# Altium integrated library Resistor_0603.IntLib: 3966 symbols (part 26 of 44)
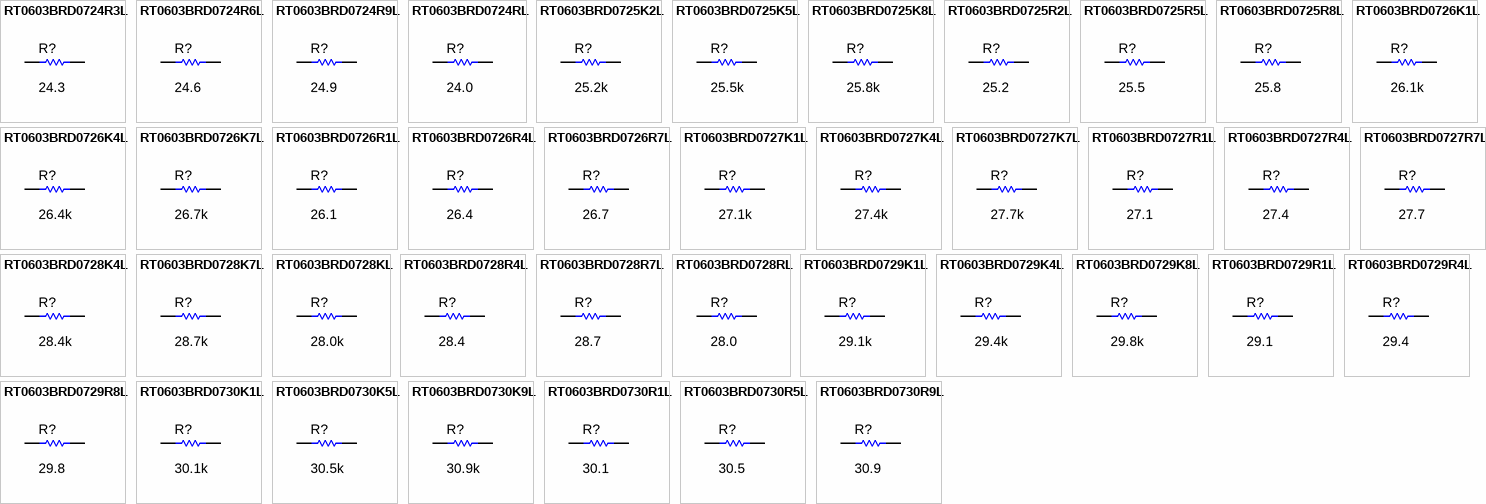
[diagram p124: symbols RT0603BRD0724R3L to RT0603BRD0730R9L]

## RT0603BRD0728R7L
designator R?  ValueDisplayed: 28.7  (hidden comment: RT0603BRD0728R7L)
RES, 28.7, 0.1%, 0.1 W, 0603; Manufacturer: Yageo America; CompType: Resistor; Value: 28.7; Value_Code: 28R7; Tolerance_%: 0.1; Value2: 0.1W; VDC_V: 75; TempCo: 25 ppm/C; SizeArea_mm2: 1.28; SizeX_mm: 1.6; SizeY_mm: 0.8; SizeZ_mm: 1; EIA_Code: E192; U/M: EA; AEC Category: Q200
signal-integrity model Resistor
simulation model Resistor
footprint 0603
footprint 0603M
footprint 0603L
footprint 0603_HV
footprint 0603S
pins: 1, 2

## RT0603BRD0728RL
designator R?  ValueDisplayed: 28.0  (hidden comment: RT0603BRD0728RL)
RES, 28.0, 0.1%, 0.1 W, 0603; Manufacturer: Yageo America; CompType: Resistor; Value: 28.0; Res_ohm: 28; Value_Code: 28R0; Tolerance_%: 0.1; Value2: 0.1W; VDC_V: 75; TempCo: 25 ppm/C; SizeArea_mm2: 1.28; SizeX_mm: 1.6; SizeY_mm: 0.8; SizeZ_mm: 1; EIA_Code: E192; U/M: EA; AEC Category: Q200
signal-integrity model Resistor
simulation model Resistor
footprint 0603
footprint 0603M
footprint 0603L
footprint 0603_HV
footprint 0603S
pins: 1, 2

## RT0603BRD0729K1L
designator R?  ValueDisplayed: 29.1k  (hidden comment: RT0603BRD0729K1L)
RES, 29.1 k, 0.1%, 0.1 W, 0603; Manufacturer: Yageo America; CompType: Resistor; Value: 29.1k; Res_ohm: 29100; Value_Code: 29k1; Tolerance_%: 0.1; Value2: 0.1W; VDC_V: 75; TempCo: 25 ppm/C; SizeArea_mm2: 1.28; SizeX_mm: 1.6; SizeY_mm: 0.8; SizeZ_mm: 1; EIA_Code: E192; U/M: EA; AEC Category: Q200
signal-integrity model Resistor
simulation model Resistor
footprint 0603
footprint 0603M
footprint 0603L
footprint 0603_HV
footprint 0603S
pins: 1, 2

## RT0603BRD0729K4L
designator R?  ValueDisplayed: 29.4k  (hidden comment: RT0603BRD0729K4L)
RES, 29.4 k, 0.1%, 0.1 W, 0603; Manufacturer: Yageo America; CompType: Resistor; Value: 29.4k; Res_ohm: 29400; Value_Code: 29k4; Tolerance_%: 0.1; Value2: 0.1W; VDC_V: 75; TempCo: 25 ppm/C; SizeArea_mm2: 1.28; SizeX_mm: 1.6; SizeY_mm: 0.8; SizeZ_mm: 1; EIA_Code: E192; U/M: EA; AEC Category: Q200
signal-integrity model Resistor
simulation model Resistor
footprint 0603
footprint 0603M
footprint 0603L
footprint 0603_HV
footprint 0603S
pins: 1, 2

## RT0603BRD0729K8L
designator R?  ValueDisplayed: 29.8k  (hidden comment: RT0603BRD0729K8L)
RES, 29.8 k, 0.1%, 0.1 W, 0603; Manufacturer: Yageo America; CompType: Resistor; Value: 29.8k; Res_ohm: 29800; Value_Code: 29k8; Tolerance_%: 0.1; Value2: 0.1W; VDC_V: 75; TempCo: 25 ppm/C; SizeArea_mm2: 1.28; SizeX_mm: 1.6; SizeY_mm: 0.8; SizeZ_mm: 1; EIA_Code: E192; U/M: EA; AEC Category: Q200
signal-integrity model Resistor
simulation model Resistor
footprint 0603
footprint 0603M
footprint 0603L
footprint 0603_HV
footprint 0603S
pins: 1, 2

## RT0603BRD0729R1L
designator R?  ValueDisplayed: 29.1  (hidden comment: RT0603BRD0729R1L)
RES, 29.1, 0.1%, 0.1 W, 0603; Manufacturer: Yageo America; CompType: Resistor; Value: 29.1; Value_Code: 29R1; Tolerance_%: 0.1; Value2: 0.1W; VDC_V: 75; TempCo: 25 ppm/C; SizeArea_mm2: 1.28; SizeX_mm: 1.6; SizeY_mm: 0.8; SizeZ_mm: 1; EIA_Code: E192; U/M: EA; AEC Category: Q200
signal-integrity model Resistor
simulation model Resistor
footprint 0603
footprint 0603M
footprint 0603L
footprint 0603_HV
footprint 0603S
pins: 1, 2

## RT0603BRD0729R4L
designator R?  ValueDisplayed: 29.4  (hidden comment: RT0603BRD0729R4L)
RES, 29.4, 0.1%, 0.1 W, 0603; Manufacturer: Yageo America; CompType: Resistor; Value: 29.4; Value_Code: 29R4; Tolerance_%: 0.1; Value2: 0.1W; VDC_V: 75; TempCo: 25 ppm/C; SizeArea_mm2: 1.28; SizeX_mm: 1.6; SizeY_mm: 0.8; SizeZ_mm: 1; EIA_Code: E192; U/M: EA; AEC Category: Q200
signal-integrity model Resistor
simulation model Resistor
footprint 0603
footprint 0603M
footprint 0603L
footprint 0603_HV
footprint 0603S
pins: 1, 2

## RT0603BRD0729R8L
designator R?  ValueDisplayed: 29.8  (hidden comment: RT0603BRD0729R8L)
RES, 29.8, 0.1%, 0.1 W, 0603; Manufacturer: Yageo America; CompType: Resistor; Value: 29.8; Value_Code: 29R8; Tolerance_%: 0.1; Value2: 0.1W; VDC_V: 75; TempCo: 25 ppm/C; SizeArea_mm2: 1.28; SizeX_mm: 1.6; SizeY_mm: 0.8; SizeZ_mm: 1; EIA_Code: E192; U/M: EA; AEC Category: Q200
signal-integrity model Resistor
simulation model Resistor
footprint 0603
footprint 0603M
footprint 0603L
footprint 0603_HV
footprint 0603S
pins: 1, 2

## RT0603BRD0730K1L
designator R?  ValueDisplayed: 30.1k  (hidden comment: RT0603BRD0730K1L)
RES, 30.1 k, 0.1%, 0.1 W, 0603; Manufacturer: Yageo America; CompType: Resistor; Value: 30.1k; Res_ohm: 30100; Value_Code: 30k1; Tolerance_%: 0.1; Value2: 0.1W; VDC_V: 75; TempCo: 25 ppm/C; SizeArea_mm2: 1.28; SizeX_mm: 1.6; SizeY_mm: 0.8; SizeZ_mm: 1; EIA_Code: E192; U/M: EA; AEC Category: Q200
signal-integrity model Resistor
simulation model Resistor
footprint 0603
footprint 0603M
footprint 0603L
footprint 0603_HV
footprint 0603S
pins: 1, 2

## RT0603BRD0730K5L
designator R?  ValueDisplayed: 30.5k  (hidden comment: RT0603BRD0730K5L)
RES, 30.5 k, 0.1%, 0.1 W, 0603; Manufacturer: Yageo America; CompType: Resistor; Value: 30.5k; Res_ohm: 30500; Value_Code: 30k5; Tolerance_%: 0.1; Value2: 0.1W; VDC_V: 75; TempCo: 25 ppm/C; SizeArea_mm2: 1.28; SizeX_mm: 1.6; SizeY_mm: 0.8; SizeZ_mm: 1; EIA_Code: E192; U/M: EA; AEC Category: Q200
signal-integrity model Resistor
simulation model Resistor
footprint 0603
footprint 0603M
footprint 0603L
footprint 0603_HV
footprint 0603S
pins: 1, 2

## RT0603BRD0730K9L
designator R?  ValueDisplayed: 30.9k  (hidden comment: RT0603BRD0730K9L)
RES, 30.9 k, 0.1%, 0.1 W, 0603; Manufacturer: Yageo America; CompType: Resistor; Value: 30.9k; Res_ohm: 30900; Value_Code: 30k9; Tolerance_%: 0.1; Value2: 0.1W; VDC_V: 75; TempCo: 25 ppm/C; SizeArea_mm2: 1.28; SizeX_mm: 1.6; SizeY_mm: 0.8; SizeZ_mm: 1; EIA_Code: E192; U/M: EA; AEC Category: Q200
signal-integrity model Resistor
simulation model Resistor
footprint 0603
footprint 0603M
footprint 0603L
footprint 0603_HV
footprint 0603S
pins: 1, 2

## RT0603BRD0730R1L
designator R?  ValueDisplayed: 30.1  (hidden comment: RT0603BRD0730R1L)
RES, 30.1, 0.1%, 0.1 W, 0603; Manufacturer: Yageo America; CompType: Resistor; Value: 30.1; Value_Code: 30R1; Tolerance_%: 0.1; Value2: 0.1W; VDC_V: 75; TempCo: 25 ppm/C; SizeArea_mm2: 1.28; SizeX_mm: 1.6; SizeY_mm: 0.8; SizeZ_mm: 1; EIA_Code: E192; U/M: EA; AEC Category: Q200
signal-integrity model Resistor
simulation model Resistor
footprint 0603
footprint 0603M
footprint 0603L
footprint 0603_HV
footprint 0603S
pins: 1, 2

## RT0603BRD0730R5L
designator R?  ValueDisplayed: 30.5  (hidden comment: RT0603BRD0730R5L)
RES, 30.5, 0.1%, 0.1 W, 0603; Manufacturer: Yageo America; CompType: Resistor; Value: 30.5; Value_Code: 30R5; Tolerance_%: 0.1; Value2: 0.1W; VDC_V: 75; TempCo: 25 ppm/C; SizeArea_mm2: 1.28; SizeX_mm: 1.6; SizeY_mm: 0.8; SizeZ_mm: 1; EIA_Code: E192; U/M: EA; AEC Category: Q200
signal-integrity model Resistor
simulation model Resistor
footprint 0603
footprint 0603M
footprint 0603L
footprint 0603_HV
footprint 0603S
pins: 1, 2

## RT0603BRD0730R9L
designator R?  ValueDisplayed: 30.9  (hidden comment: RT0603BRD0730R9L)
RES, 30.9, 0.1%, 0.1 W, 0603; Manufacturer: Yageo America; CompType: Resistor; Value: 30.9; Value_Code: 30R9; Tolerance_%: 0.1; Value2: 0.1W; VDC_V: 75; TempCo: 25 ppm/C; SizeArea_mm2: 1.28; SizeX_mm: 1.6; SizeY_mm: 0.8; SizeZ_mm: 1; EIA_Code: E192; U/M: EA; AEC Category: Q200
signal-integrity model Resistor
simulation model Resistor
footprint 0603
footprint 0603M
footprint 0603L
footprint 0603_HV
footprint 0603S
pins: 1, 2

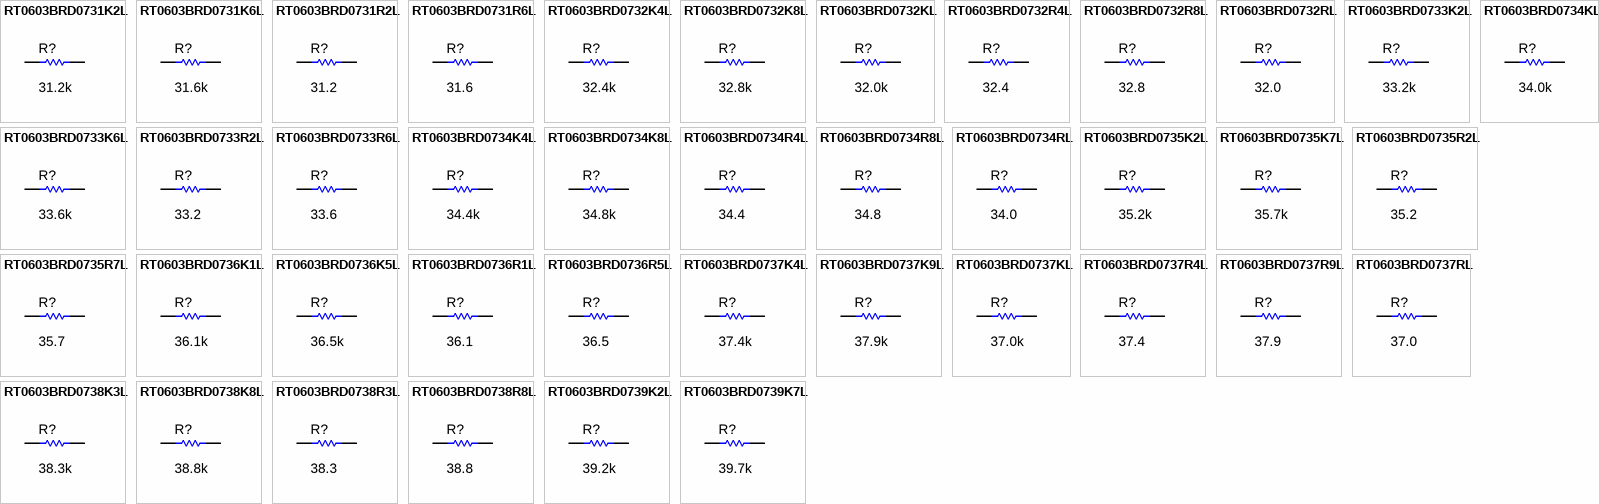
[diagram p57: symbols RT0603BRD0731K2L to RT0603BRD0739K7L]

## RT0603BRD0731K2L
designator R?  ValueDisplayed: 31.2k  (hidden comment: RT0603BRD0731K2L)
RES, 31.2 k, 0.1%, 0.1 W, 0603; Manufacturer: Yageo America; CompType: Resistor; Value: 31.2k; Res_ohm: 31200; Value_Code: 31k2; Tolerance_%: 0.1; Value2: 0.1W; VDC_V: 75; TempCo: 25 ppm/C; SizeArea_mm2: 1.28; SizeX_mm: 1.6; SizeY_mm: 0.8; SizeZ_mm: 1; EIA_Code: E192; U/M: EA; AEC Category: Q200
signal-integrity model Resistor
simulation model Resistor
footprint 0603
footprint 0603M
footprint 0603L
footprint 0603_HV
footprint 0603S
pins: 1, 2

## RT0603BRD0731K6L
designator R?  ValueDisplayed: 31.6k  (hidden comment: RT0603BRD0731K6L)
RES, 31.6 k, 0.1%, 0.1 W, 0603; Manufacturer: Yageo America; CompType: Resistor; Value: 31.6k; Res_ohm: 31600; Value_Code: 31k6; Tolerance_%: 0.1; Value2: 0.1W; VDC_V: 75; TempCo: 25 ppm/C; SizeArea_mm2: 1.28; SizeX_mm: 1.6; SizeY_mm: 0.8; SizeZ_mm: 1; EIA_Code: E192; U/M: EA; AEC Category: Q200
signal-integrity model Resistor
simulation model Resistor
footprint 0603
footprint 0603M
footprint 0603L
footprint 0603_HV
footprint 0603S
pins: 1, 2

## RT0603BRD0731R2L
designator R?  ValueDisplayed: 31.2  (hidden comment: RT0603BRD0731R2L)
RES, 31.2, 0.1%, 0.1 W, 0603; Manufacturer: Yageo America; CompType: Resistor; Value: 31.2; Value_Code: 31R2; Tolerance_%: 0.1; Value2: 0.1W; VDC_V: 75; TempCo: 25 ppm/C; SizeArea_mm2: 1.28; SizeX_mm: 1.6; SizeY_mm: 0.8; SizeZ_mm: 1; EIA_Code: E192; U/M: EA; AEC Category: Q200
signal-integrity model Resistor
simulation model Resistor
footprint 0603
footprint 0603M
footprint 0603L
footprint 0603_HV
footprint 0603S
pins: 1, 2

## RT0603BRD0731R6L
designator R?  ValueDisplayed: 31.6  (hidden comment: RT0603BRD0731R6L)
RES, 31.6, 0.1%, 0.1 W, 0603; Manufacturer: Yageo America; CompType: Resistor; Value: 31.6; Value_Code: 31R6; Tolerance_%: 0.1; Value2: 0.1W; VDC_V: 75; TempCo: 25 ppm/C; SizeArea_mm2: 1.28; SizeX_mm: 1.6; SizeY_mm: 0.8; SizeZ_mm: 1; EIA_Code: E192; U/M: EA; AEC Category: Q200
signal-integrity model Resistor
simulation model Resistor
footprint 0603
footprint 0603M
footprint 0603L
footprint 0603_HV
footprint 0603S
pins: 1, 2

## RT0603BRD0732K4L
designator R?  ValueDisplayed: 32.4k  (hidden comment: RT0603BRD0732K4L)
RES, 32.4 k, 0.1%, 0.1 W, 0603; Manufacturer: Yageo America; CompType: Resistor; Value: 32.4k; Res_ohm: 32400; Value_Code: 32k4; Tolerance_%: 0.1; Value2: 0.1W; VDC_V: 75; TempCo: 25 ppm/C; SizeArea_mm2: 1.28; SizeX_mm: 1.6; SizeY_mm: 0.8; SizeZ_mm: 1; EIA_Code: E192; U/M: EA; AEC Category: Q200
signal-integrity model Resistor
simulation model Resistor
footprint 0603
footprint 0603M
footprint 0603L
footprint 0603_HV
footprint 0603S
pins: 1, 2

## RT0603BRD0732K8L
designator R?  ValueDisplayed: 32.8k  (hidden comment: RT0603BRD0732K8L)
RES, 32.8 k, 0.1%, 0.1 W, 0603; Manufacturer: Yageo America; CompType: Resistor; Value: 32.8k; Res_ohm: 32800; Value_Code: 32k8; Tolerance_%: 0.1; Value2: 0.1W; VDC_V: 75; TempCo: 25 ppm/C; SizeArea_mm2: 1.28; SizeX_mm: 1.6; SizeY_mm: 0.8; SizeZ_mm: 1; EIA_Code: E192; U/M: EA; AEC Category: Q200
signal-integrity model Resistor
simulation model Resistor
footprint 0603
footprint 0603M
footprint 0603L
footprint 0603_HV
footprint 0603S
pins: 1, 2

## RT0603BRD0732KL
designator R?  ValueDisplayed: 32.0k  (hidden comment: RT0603BRD0732KL)
RES, 32.0 k, 0.1%, 0.1 W, 0603; Manufacturer: Yageo America; CompType: Resistor; Value: 32.0k; Res_ohm: 32000; Value_Code: 32k0; Tolerance_%: 0.1; Value2: 0.1W; VDC_V: 75; TempCo: 25 ppm/C; SizeArea_mm2: 1.28; SizeX_mm: 1.6; SizeY_mm: 0.8; SizeZ_mm: 1; EIA_Code: E192; U/M: EA; AEC Category: Q200
signal-integrity model Resistor
simulation model Resistor
footprint 0603
footprint 0603M
footprint 0603L
footprint 0603_HV
footprint 0603S
pins: 1, 2

## RT0603BRD0732R4L
designator R?  ValueDisplayed: 32.4  (hidden comment: RT0603BRD0732R4L)
RES, 32.4, 0.1%, 0.1 W, 0603; Manufacturer: Yageo America; CompType: Resistor; Value: 32.4; Value_Code: 32R4; Tolerance_%: 0.1; Value2: 0.1W; VDC_V: 75; TempCo: 25 ppm/C; SizeArea_mm2: 1.28; SizeX_mm: 1.6; SizeY_mm: 0.8; SizeZ_mm: 1; EIA_Code: E192; U/M: EA; AEC Category: Q200
signal-integrity model Resistor
simulation model Resistor
footprint 0603
footprint 0603M
footprint 0603L
footprint 0603_HV
footprint 0603S
pins: 1, 2

## RT0603BRD0732R8L
designator R?  ValueDisplayed: 32.8  (hidden comment: RT0603BRD0732R8L)
RES, 32.8, 0.1%, 0.1 W, 0603; Manufacturer: Yageo America; CompType: Resistor; Value: 32.8; Value_Code: 32R8; Tolerance_%: 0.1; Value2: 0.1W; VDC_V: 75; TempCo: 25 ppm/C; SizeArea_mm2: 1.28; SizeX_mm: 1.6; SizeY_mm: 0.8; SizeZ_mm: 1; EIA_Code: E192; U/M: EA; AEC Category: Q200
signal-integrity model Resistor
simulation model Resistor
footprint 0603
footprint 0603M
footprint 0603L
footprint 0603_HV
footprint 0603S
pins: 1, 2

## RT0603BRD0732RL
designator R?  ValueDisplayed: 32.0  (hidden comment: RT0603BRD0732RL)
RES, 32.0, 0.1%, 0.1 W, 0603; Manufacturer: Yageo America; CompType: Resistor; Value: 32.0; Res_ohm: 32; Value_Code: 32R0; Tolerance_%: 0.1; Value2: 0.1W; VDC_V: 75; TempCo: 25 ppm/C; SizeArea_mm2: 1.28; SizeX_mm: 1.6; SizeY_mm: 0.8; SizeZ_mm: 1; EIA_Code: E192; U/M: EA; AEC Category: Q200
signal-integrity model Resistor
simulation model Resistor
footprint 0603
footprint 0603M
footprint 0603L
footprint 0603_HV
footprint 0603S
pins: 1, 2

## RT0603BRD0733K2L
designator R?  ValueDisplayed: 33.2k  (hidden comment: RT0603BRD0733K2L)
RES, 33.2 k, 0.1%, 0.1 W, 0603; Manufacturer: Yageo America; CompType: Resistor; Value: 33.2k; Res_ohm: 33200; Value_Code: 33k2; Tolerance_%: 0.1; Value2: 0.1W; VDC_V: 75; TempCo: 25 ppm/C; SizeArea_mm2: 1.28; SizeX_mm: 1.6; SizeY_mm: 0.8; SizeZ_mm: 1; EIA_Code: E192; U/M: EA; AEC Category: Q200
signal-integrity model Resistor
simulation model Resistor
footprint 0603
footprint 0603M
footprint 0603L
footprint 0603_HV
footprint 0603S
pins: 1, 2

## RT0603BRD0733K6L
designator R?  ValueDisplayed: 33.6k  (hidden comment: RT0603BRD0733K6L)
RES, 33.6 k, 0.1%, 0.1 W, 0603; Manufacturer: Yageo America; CompType: Resistor; Value: 33.6k; Res_ohm: 33600; Value_Code: 33k6; Tolerance_%: 0.1; Value2: 0.1W; VDC_V: 75; TempCo: 25 ppm/C; SizeArea_mm2: 1.28; SizeX_mm: 1.6; SizeY_mm: 0.8; SizeZ_mm: 1; EIA_Code: E192; U/M: EA; AEC Category: Q200
signal-integrity model Resistor
simulation model Resistor
footprint 0603
footprint 0603M
footprint 0603L
footprint 0603_HV
footprint 0603S
pins: 1, 2

## RT0603BRD0733R2L
designator R?  ValueDisplayed: 33.2  (hidden comment: RT0603BRD0733R2L)
RES, 33.2, 0.1%, 0.1 W, 0603; Manufacturer: Yageo America; CompType: Resistor; Value: 33.2; Value_Code: 33R2; Tolerance_%: 0.1; Value2: 0.1W; VDC_V: 75; TempCo: 25 ppm/C; SizeArea_mm2: 1.28; SizeX_mm: 1.6; SizeY_mm: 0.8; SizeZ_mm: 1; EIA_Code: E192; U/M: EA; AEC Category: Q200
signal-integrity model Resistor
simulation model Resistor
footprint 0603
footprint 0603M
footprint 0603L
footprint 0603_HV
footprint 0603S
pins: 1, 2

## RT0603BRD0733R6L
designator R?  ValueDisplayed: 33.6  (hidden comment: RT0603BRD0733R6L)
RES, 33.6, 0.1%, 0.1 W, 0603; Manufacturer: Yageo America; CompType: Resistor; Value: 33.6; Value_Code: 33R6; Tolerance_%: 0.1; Value2: 0.1W; VDC_V: 75; TempCo: 25 ppm/C; SizeArea_mm2: 1.28; SizeX_mm: 1.6; SizeY_mm: 0.8; SizeZ_mm: 1; EIA_Code: E192; U/M: EA; AEC Category: Q200
signal-integrity model Resistor
simulation model Resistor
footprint 0603
footprint 0603M
footprint 0603L
footprint 0603_HV
footprint 0603S
pins: 1, 2

## RT0603BRD0734K4L
designator R?  ValueDisplayed: 34.4k  (hidden comment: RT0603BRD0734K4L)
RES, 34.4 k, 0.1%, 0.1 W, 0603; Manufacturer: Yageo America; CompType: Resistor; Value: 34.4k; Res_ohm: 34400; Value_Code: 34k4; Tolerance_%: 0.1; Value2: 0.1W; VDC_V: 75; TempCo: 25 ppm/C; SizeArea_mm2: 1.28; SizeX_mm: 1.6; SizeY_mm: 0.8; SizeZ_mm: 1; EIA_Code: E192; U/M: EA; AEC Category: Q200
signal-integrity model Resistor
simulation model Resistor
footprint 0603
footprint 0603M
footprint 0603L
footprint 0603_HV
footprint 0603S
pins: 1, 2

## RT0603BRD0734K8L
designator R?  ValueDisplayed: 34.8k  (hidden comment: RT0603BRD0734K8L)
RES, 34.8 k, 0.1%, 0.1 W, 0603; Manufacturer: Yageo America; CompType: Resistor; Value: 34.8k; Res_ohm: 34800; Value_Code: 34k8; Tolerance_%: 0.1; Value2: 0.1W; VDC_V: 75; TempCo: 25 ppm/C; SizeArea_mm2: 1.28; SizeX_mm: 1.6; SizeY_mm: 0.8; SizeZ_mm: 1; EIA_Code: E192; U/M: EA; AEC Category: Q200
signal-integrity model Resistor
simulation model Resistor
footprint 0603
footprint 0603M
footprint 0603L
footprint 0603_HV
footprint 0603S
pins: 1, 2

## RT0603BRD0734KL
designator R?  ValueDisplayed: 34.0k  (hidden comment: RT0603BRD0734KL)
RES, 34.0 k, 0.1%, 0.1 W, 0603; Manufacturer: Yageo America; CompType: Resistor; Value: 34.0k; Res_ohm: 34000; Value_Code: 34k0; Tolerance_%: 0.1; Value2: 0.1W; VDC_V: 75; TempCo: 25 ppm/C; SizeArea_mm2: 1.28; SizeX_mm: 1.6; SizeY_mm: 0.8; SizeZ_mm: 1; EIA_Code: E192; U/M: EA; AEC Category: Q200
signal-integrity model Resistor
simulation model Resistor
footprint 0603
footprint 0603M
footprint 0603L
footprint 0603_HV
footprint 0603S
pins: 1, 2

## RT0603BRD0734R4L
designator R?  ValueDisplayed: 34.4  (hidden comment: RT0603BRD0734R4L)
RES, 34.4, 0.1%, 0.1 W, 0603; Manufacturer: Yageo America; CompType: Resistor; Value: 34.4; Value_Code: 34R4; Tolerance_%: 0.1; Value2: 0.1W; VDC_V: 75; TempCo: 25 ppm/C; SizeArea_mm2: 1.28; SizeX_mm: 1.6; SizeY_mm: 0.8; SizeZ_mm: 1; EIA_Code: E192; U/M: EA; AEC Category: Q200
signal-integrity model Resistor
simulation model Resistor
footprint 0603
footprint 0603M
footprint 0603L
footprint 0603_HV
footprint 0603S
pins: 1, 2

## RT0603BRD0734R8L
designator R?  ValueDisplayed: 34.8  (hidden comment: RT0603BRD0734R8L)
RES, 34.8, 0.1%, 0.1 W, 0603; Manufacturer: Yageo America; CompType: Resistor; Value: 34.8; Value_Code: 34R8; Tolerance_%: 0.1; Value2: 0.1W; VDC_V: 75; TempCo: 25 ppm/C; SizeArea_mm2: 1.28; SizeX_mm: 1.6; SizeY_mm: 0.8; SizeZ_mm: 1; EIA_Code: E192; U/M: EA; AEC Category: Q200
signal-integrity model Resistor
simulation model Resistor
footprint 0603
footprint 0603M
footprint 0603L
footprint 0603_HV
footprint 0603S
pins: 1, 2

## RT0603BRD0734RL
designator R?  ValueDisplayed: 34.0  (hidden comment: RT0603BRD0734RL)
RES, 34.0, 0.1%, 0.1 W, 0603; Manufacturer: Yageo America; CompType: Resistor; Value: 34.0; Res_ohm: 34; Value_Code: 34R0; Tolerance_%: 0.1; Value2: 0.1W; VDC_V: 75; TempCo: 25 ppm/C; SizeArea_mm2: 1.28; SizeX_mm: 1.6; SizeY_mm: 0.8; SizeZ_mm: 1; EIA_Code: E192; U/M: EA; AEC Category: Q200
signal-integrity model Resistor
simulation model Resistor
footprint 0603
footprint 0603M
footprint 0603L
footprint 0603_HV
footprint 0603S
pins: 1, 2

## RT0603BRD0735K2L
designator R?  ValueDisplayed: 35.2k  (hidden comment: RT0603BRD0735K2L)
RES, 35.2 k, 0.1%, 0.1 W, 0603; Manufacturer: Yageo America; CompType: Resistor; Value: 35.2k; Res_ohm: 35200; Value_Code: 35k2; Tolerance_%: 0.1; Value2: 0.1W; VDC_V: 75; TempCo: 25 ppm/C; SizeArea_mm2: 1.28; SizeX_mm: 1.6; SizeY_mm: 0.8; SizeZ_mm: 1; EIA_Code: E192; U/M: EA; AEC Category: Q200
signal-integrity model Resistor
simulation model Resistor
footprint 0603
footprint 0603M
footprint 0603L
footprint 0603_HV
footprint 0603S
pins: 1, 2

## RT0603BRD0735K7L
designator R?  ValueDisplayed: 35.7k  (hidden comment: RT0603BRD0735K7L)
RES, 35.7 k, 0.1%, 0.1 W, 0603; Manufacturer: Yageo America; CompType: Resistor; Value: 35.7k; Res_ohm: 35700; Value_Code: 35k7; Tolerance_%: 0.1; Value2: 0.1W; VDC_V: 75; TempCo: 25 ppm/C; SizeArea_mm2: 1.28; SizeX_mm: 1.6; SizeY_mm: 0.8; SizeZ_mm: 1; EIA_Code: E192; U/M: EA; AEC Category: Q200
signal-integrity model Resistor
simulation model Resistor
footprint 0603
footprint 0603M
footprint 0603L
footprint 0603_HV
footprint 0603S
pins: 1, 2

## RT0603BRD0735R2L
designator R?  ValueDisplayed: 35.2  (hidden comment: RT0603BRD0735R2L)
RES, 35.2, 0.1%, 0.1 W, 0603; Manufacturer: Yageo America; CompType: Resistor; Value: 35.2; Value_Code: 35R2; Tolerance_%: 0.1; Value2: 0.1W; VDC_V: 75; TempCo: 25 ppm/C; SizeArea_mm2: 1.28; SizeX_mm: 1.6; SizeY_mm: 0.8; SizeZ_mm: 1; EIA_Code: E192; U/M: EA; AEC Category: Q200
signal-integrity model Resistor
simulation model Resistor
footprint 0603
footprint 0603M
footprint 0603L
footprint 0603_HV
footprint 0603S
pins: 1, 2

## RT0603BRD0735R7L
designator R?  ValueDisplayed: 35.7  (hidden comment: RT0603BRD0735R7L)
RES, 35.7, 0.1%, 0.1 W, 0603; Manufacturer: Yageo America; CompType: Resistor; Value: 35.7; Value_Code: 35R7; Tolerance_%: 0.1; Value2: 0.1W; VDC_V: 75; TempCo: 25 ppm/C; SizeArea_mm2: 1.28; SizeX_mm: 1.6; SizeY_mm: 0.8; SizeZ_mm: 1; EIA_Code: E192; U/M: EA; AEC Category: Q200
signal-integrity model Resistor
simulation model Resistor
footprint 0603
footprint 0603M
footprint 0603L
footprint 0603_HV
footprint 0603S
pins: 1, 2

## RT0603BRD0736K1L
designator R?  ValueDisplayed: 36.1k  (hidden comment: RT0603BRD0736K1L)
RES, 36.1 k, 0.1%, 0.1 W, 0603; Manufacturer: Yageo America; CompType: Resistor; Value: 36.1k; Res_ohm: 36100; Value_Code: 36k1; Tolerance_%: 0.1; Value2: 0.1W; VDC_V: 75; TempCo: 25 ppm/C; SizeArea_mm2: 1.28; SizeX_mm: 1.6; SizeY_mm: 0.8; SizeZ_mm: 1; EIA_Code: E192; U/M: EA; AEC Category: Q200
signal-integrity model Resistor
simulation model Resistor
footprint 0603
footprint 0603M
footprint 0603L
footprint 0603_HV
footprint 0603S
pins: 1, 2

## RT0603BRD0736K5L
designator R?  ValueDisplayed: 36.5k  (hidden comment: RT0603BRD0736K5L)
RES, 36.5 k, 0.1%, 0.1 W, 0603; Manufacturer: Yageo America; CompType: Resistor; Value: 36.5k; Res_ohm: 36500; Value_Code: 36k5; Tolerance_%: 0.1; Value2: 0.1W; VDC_V: 75; TempCo: 25 ppm/C; SizeArea_mm2: 1.28; SizeX_mm: 1.6; SizeY_mm: 0.8; SizeZ_mm: 1; EIA_Code: E192; U/M: EA; AEC Category: Q200
signal-integrity model Resistor
simulation model Resistor
footprint 0603
footprint 0603M
footprint 0603L
footprint 0603_HV
footprint 0603S
pins: 1, 2

## RT0603BRD0736R1L
designator R?  ValueDisplayed: 36.1  (hidden comment: RT0603BRD0736R1L)
RES, 36.1, 0.1%, 0.1 W, 0603; Manufacturer: Yageo America; CompType: Resistor; Value: 36.1; Value_Code: 36R1; Tolerance_%: 0.1; Value2: 0.1W; VDC_V: 75; TempCo: 25 ppm/C; SizeArea_mm2: 1.28; SizeX_mm: 1.6; SizeY_mm: 0.8; SizeZ_mm: 1; EIA_Code: E192; U/M: EA; AEC Category: Q200
signal-integrity model Resistor
simulation model Resistor
footprint 0603
footprint 0603M
footprint 0603L
footprint 0603_HV
footprint 0603S
pins: 1, 2

## RT0603BRD0736R5L
designator R?  ValueDisplayed: 36.5  (hidden comment: RT0603BRD0736R5L)
RES, 36.5, 0.1%, 0.1 W, 0603; Manufacturer: Yageo America; CompType: Resistor; Value: 36.5; Value_Code: 36R5; Tolerance_%: 0.1; Value2: 0.1W; VDC_V: 75; TempCo: 25 ppm/C; SizeArea_mm2: 1.28; SizeX_mm: 1.6; SizeY_mm: 0.8; SizeZ_mm: 1; EIA_Code: E192; U/M: EA; AEC Category: Q200
signal-integrity model Resistor
simulation model Resistor
footprint 0603
footprint 0603M
footprint 0603L
footprint 0603_HV
footprint 0603S
pins: 1, 2

## RT0603BRD0737K4L
designator R?  ValueDisplayed: 37.4k  (hidden comment: RT0603BRD0737K4L)
RES, 37.4 k, 0.1%, 0.1 W, 0603; Manufacturer: Yageo America; CompType: Resistor; Value: 37.4k; Res_ohm: 37400; Value_Code: 37k4; Tolerance_%: 0.1; Value2: 0.1W; VDC_V: 75; TempCo: 25 ppm/C; SizeArea_mm2: 1.28; SizeX_mm: 1.6; SizeY_mm: 0.8; SizeZ_mm: 1; EIA_Code: E192; U/M: EA; AEC Category: Q200
signal-integrity model Resistor
simulation model Resistor
footprint 0603
footprint 0603M
footprint 0603L
footprint 0603_HV
footprint 0603S
pins: 1, 2

## RT0603BRD0737K9L
designator R?  ValueDisplayed: 37.9k  (hidden comment: RT0603BRD0737K9L)
RES, 37.9 k, 0.1%, 0.1 W, 0603; Manufacturer: Yageo America; CompType: Resistor; Value: 37.9k; Res_ohm: 37900; Value_Code: 37k9; Tolerance_%: 0.1; Value2: 0.1W; VDC_V: 75; TempCo: 25 ppm/C; SizeArea_mm2: 1.28; SizeX_mm: 1.6; SizeY_mm: 0.8; SizeZ_mm: 1; EIA_Code: E192; U/M: EA; AEC Category: Q200
signal-integrity model Resistor
simulation model Resistor
footprint 0603
footprint 0603M
footprint 0603L
footprint 0603_HV
footprint 0603S
pins: 1, 2

## RT0603BRD0737KL
designator R?  ValueDisplayed: 37.0k  (hidden comment: RT0603BRD0737KL)
RES, 37.0 k, 0.1%, 0.1 W, 0603; Manufacturer: Yageo America; CompType: Resistor; Value: 37.0k; Res_ohm: 37000; Value_Code: 37k0; Tolerance_%: 0.1; Value2: 0.1W; VDC_V: 75; TempCo: 25 ppm/C; SizeArea_mm2: 1.28; SizeX_mm: 1.6; SizeY_mm: 0.8; SizeZ_mm: 1; EIA_Code: E192; U/M: EA; AEC Category: Q200
signal-integrity model Resistor
simulation model Resistor
footprint 0603
footprint 0603M
footprint 0603L
footprint 0603_HV
footprint 0603S
pins: 1, 2

## RT0603BRD0737R4L
designator R?  ValueDisplayed: 37.4  (hidden comment: RT0603BRD0737R4L)
RES, 37.4, 0.1%, 0.1 W, 0603; Manufacturer: Yageo America; CompType: Resistor; Value: 37.4; Value_Code: 37R4; Tolerance_%: 0.1; Value2: 0.1W; VDC_V: 75; TempCo: 25 ppm/C; SizeArea_mm2: 1.28; SizeX_mm: 1.6; SizeY_mm: 0.8; SizeZ_mm: 1; EIA_Code: E192; U/M: EA; AEC Category: Q200
signal-integrity model Resistor
simulation model Resistor
footprint 0603
footprint 0603M
footprint 0603L
footprint 0603_HV
footprint 0603S
pins: 1, 2

## RT0603BRD0737R9L
designator R?  ValueDisplayed: 37.9  (hidden comment: RT0603BRD0737R9L)
RES, 37.9, 0.1%, 0.1 W, 0603; Manufacturer: Yageo America; CompType: Resistor; Value: 37.9; Value_Code: 37R9; Tolerance_%: 0.1; Value2: 0.1W; VDC_V: 75; TempCo: 25 ppm/C; SizeArea_mm2: 1.28; SizeX_mm: 1.6; SizeY_mm: 0.8; SizeZ_mm: 1; EIA_Code: E192; U/M: EA; AEC Category: Q200
signal-integrity model Resistor
simulation model Resistor
footprint 0603
footprint 0603M
footprint 0603L
footprint 0603_HV
footprint 0603S
pins: 1, 2

## RT0603BRD0737RL
designator R?  ValueDisplayed: 37.0  (hidden comment: RT0603BRD0737RL)
RES, 37.0, 0.1%, 0.1 W, 0603; Manufacturer: Yageo America; CompType: Resistor; Value: 37.0; Res_ohm: 37; Value_Code: 37R0; Tolerance_%: 0.1; Value2: 0.1W; VDC_V: 75; TempCo: 25 ppm/C; SizeArea_mm2: 1.28; SizeX_mm: 1.6; SizeY_mm: 0.8; SizeZ_mm: 1; EIA_Code: E192; U/M: EA; AEC Category: Q200
signal-integrity model Resistor
simulation model Resistor
footprint 0603
footprint 0603M
footprint 0603L
footprint 0603_HV
footprint 0603S
pins: 1, 2

## RT0603BRD0738K3L
designator R?  ValueDisplayed: 38.3k  (hidden comment: RT0603BRD0738K3L)
RES, 38.3 k, 0.1%, 0.1 W, 0603; Manufacturer: Yageo America; CompType: Resistor; Value: 38.3k; Res_ohm: 38300; Value_Code: 38k3; Tolerance_%: 0.1; Value2: 0.1W; VDC_V: 75; TempCo: 25 ppm/C; SizeArea_mm2: 1.28; SizeX_mm: 1.6; SizeY_mm: 0.8; SizeZ_mm: 1; EIA_Code: E192; U/M: EA; AEC Category: Q200
signal-integrity model Resistor
simulation model Resistor
footprint 0603
footprint 0603M
footprint 0603L
footprint 0603_HV
footprint 0603S
pins: 1, 2

## RT0603BRD0738K8L
designator R?  ValueDisplayed: 38.8k  (hidden comment: RT0603BRD0738K8L)
RES, 38.8 k, 0.1%, 0.1 W, 0603; Manufacturer: Yageo America; CompType: Resistor; Value: 38.8k; Res_ohm: 38800; Value_Code: 38k8; Tolerance_%: 0.1; Value2: 0.1W; VDC_V: 75; TempCo: 25 ppm/C; SizeArea_mm2: 1.28; SizeX_mm: 1.6; SizeY_mm: 0.8; SizeZ_mm: 1; EIA_Code: E192; U/M: EA; AEC Category: Q200
signal-integrity model Resistor
simulation model Resistor
footprint 0603
footprint 0603M
footprint 0603L
footprint 0603_HV
footprint 0603S
pins: 1, 2

## RT0603BRD0738R3L
designator R?  ValueDisplayed: 38.3  (hidden comment: RT0603BRD0738R3L)
RES, 38.3, 0.1%, 0.1 W, 0603; Manufacturer: Yageo America; CompType: Resistor; Value: 38.3; Value_Code: 38R3; Tolerance_%: 0.1; Value2: 0.1W; VDC_V: 75; TempCo: 25 ppm/C; SizeArea_mm2: 1.28; SizeX_mm: 1.6; SizeY_mm: 0.8; SizeZ_mm: 1; EIA_Code: E192; U/M: EA; AEC Category: Q200
signal-integrity model Resistor
simulation model Resistor
footprint 0603
footprint 0603M
footprint 0603L
footprint 0603_HV
footprint 0603S
pins: 1, 2

## RT0603BRD0738R8L
designator R?  ValueDisplayed: 38.8  (hidden comment: RT0603BRD0738R8L)
RES, 38.8, 0.1%, 0.1 W, 0603; Manufacturer: Yageo America; CompType: Resistor; Value: 38.8; Value_Code: 38R8; Tolerance_%: 0.1; Value2: 0.1W; VDC_V: 75; TempCo: 25 ppm/C; SizeArea_mm2: 1.28; SizeX_mm: 1.6; SizeY_mm: 0.8; SizeZ_mm: 1; EIA_Code: E192; U/M: EA; AEC Category: Q200
signal-integrity model Resistor
simulation model Resistor
footprint 0603
footprint 0603M
footprint 0603L
footprint 0603_HV
footprint 0603S
pins: 1, 2

## RT0603BRD0739K2L
designator R?  ValueDisplayed: 39.2k  (hidden comment: RT0603BRD0739K2L)
RES, 39.2 k, 0.1%, 0.1 W, 0603; Manufacturer: Yageo America; CompType: Resistor; Value: 39.2k; Res_ohm: 39200; Value_Code: 39k2; Tolerance_%: 0.1; Value2: 0.1W; VDC_V: 75; TempCo: 25 ppm/C; SizeArea_mm2: 1.28; SizeX_mm: 1.6; SizeY_mm: 0.8; SizeZ_mm: 1; EIA_Code: E192; U/M: EA; AEC Category: Q200
signal-integrity model Resistor
simulation model Resistor
footprint 0603
footprint 0603M
footprint 0603L
footprint 0603_HV
footprint 0603S
pins: 1, 2

## RT0603BRD0739K7L
designator R?  ValueDisplayed: 39.7k  (hidden comment: RT0603BRD0739K7L)
RES, 39.7 k, 0.1%, 0.1 W, 0603; Manufacturer: Yageo America; CompType: Resistor; Value: 39.7k; Res_ohm: 39700; Value_Code: 39k7; Tolerance_%: 0.1; Value2: 0.1W; VDC_V: 75; TempCo: 25 ppm/C; SizeArea_mm2: 1.28; SizeX_mm: 1.6; SizeY_mm: 0.8; SizeZ_mm: 1; EIA_Code: E192; U/M: EA; AEC Category: Q200
signal-integrity model Resistor
simulation model Resistor
footprint 0603
footprint 0603M
footprint 0603L
footprint 0603_HV
footprint 0603S
pins: 1, 2

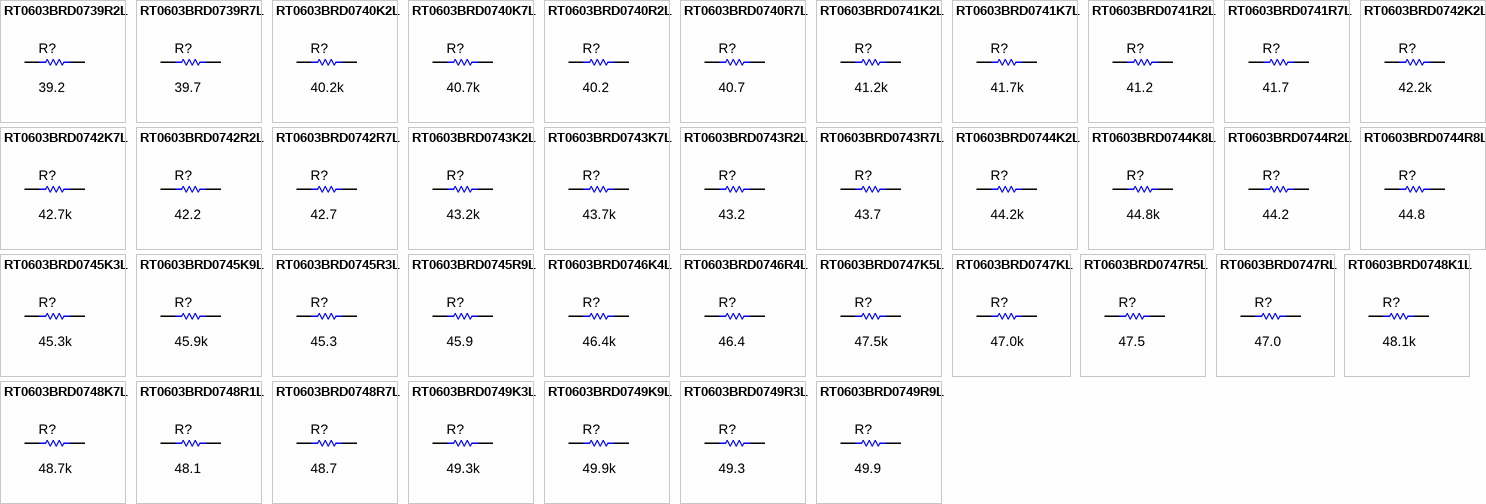
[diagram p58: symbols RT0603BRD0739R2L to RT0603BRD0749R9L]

## RT0603BRD0739R2L
designator R?  ValueDisplayed: 39.2  (hidden comment: RT0603BRD0739R2L)
RES, 39.2, 0.1%, 0.1 W, 0603; Manufacturer: Yageo America; CompType: Resistor; Value: 39.2; Value_Code: 39R2; Tolerance_%: 0.1; Value2: 0.1W; VDC_V: 75; TempCo: 25 ppm/C; SizeArea_mm2: 1.28; SizeX_mm: 1.6; SizeY_mm: 0.8; SizeZ_mm: 1; EIA_Code: E192; U/M: EA; AEC Category: Q200
signal-integrity model Resistor
simulation model Resistor
footprint 0603
footprint 0603M
footprint 0603L
footprint 0603_HV
footprint 0603S
pins: 1, 2

## RT0603BRD0739R7L
designator R?  ValueDisplayed: 39.7  (hidden comment: RT0603BRD0739R7L)
RES, 39.7, 0.1%, 0.1 W, 0603; Manufacturer: Yageo America; CompType: Resistor; Value: 39.7; Value_Code: 39R7; Tolerance_%: 0.1; Value2: 0.1W; VDC_V: 75; TempCo: 25 ppm/C; SizeArea_mm2: 1.28; SizeX_mm: 1.6; SizeY_mm: 0.8; SizeZ_mm: 1; EIA_Code: E192; U/M: EA; AEC Category: Q200
signal-integrity model Resistor
simulation model Resistor
footprint 0603
footprint 0603M
footprint 0603L
footprint 0603_HV
footprint 0603S
pins: 1, 2

## RT0603BRD0740K2L
designator R?  ValueDisplayed: 40.2k  (hidden comment: RT0603BRD0740K2L)
RES, 40.2 k, 0.1%, 0.1 W, 0603; Manufacturer: Yageo America; CompType: Resistor; Value: 40.2k; Res_ohm: 40200; Value_Code: 40k2; Tolerance_%: 0.1; Value2: 0.1W; VDC_V: 75; TempCo: 25 ppm/C; SizeArea_mm2: 1.28; SizeX_mm: 1.6; SizeY_mm: 0.8; SizeZ_mm: 1; EIA_Code: E192; U/M: EA; AEC Category: Q200; Green_Lifecycle: Active; Green_REACh: Passed
signal-integrity model Resistor
simulation model Resistor
footprint 0603
footprint 0603M
footprint 0603L
footprint 0603_HV
footprint 0603S
pins: 1, 2

## RT0603BRD0740K7L
designator R?  ValueDisplayed: 40.7k  (hidden comment: RT0603BRD0740K7L)
RES, 40.7 k, 0.1%, 0.1 W, 0603; Manufacturer: Yageo America; CompType: Resistor; Value: 40.7k; Res_ohm: 40700; Value_Code: 40k7; Tolerance_%: 0.1; Value2: 0.1W; VDC_V: 75; TempCo: 25 ppm/C; SizeArea_mm2: 1.28; SizeX_mm: 1.6; SizeY_mm: 0.8; SizeZ_mm: 1; EIA_Code: E192; U/M: EA; AEC Category: Q200
signal-integrity model Resistor
simulation model Resistor
footprint 0603
footprint 0603M
footprint 0603L
footprint 0603_HV
footprint 0603S
pins: 1, 2

## RT0603BRD0740R2L
designator R?  ValueDisplayed: 40.2  (hidden comment: RT0603BRD0740R2L)
RES, 40.2, 0.1%, 0.1 W, 0603; Manufacturer: Yageo America; CompType: Resistor; Value: 40.2; Value_Code: 40R2; Tolerance_%: 0.1; Value2: 0.1W; VDC_V: 75; TempCo: 25 ppm/C; SizeArea_mm2: 1.28; SizeX_mm: 1.6; SizeY_mm: 0.8; SizeZ_mm: 1; EIA_Code: E192; U/M: EA; AEC Category: Q200
signal-integrity model Resistor
simulation model Resistor
footprint 0603
footprint 0603M
footprint 0603L
footprint 0603_HV
footprint 0603S
pins: 1, 2

## RT0603BRD0740R7L
designator R?  ValueDisplayed: 40.7  (hidden comment: RT0603BRD0740R7L)
RES, 40.7, 0.1%, 0.1 W, 0603; Manufacturer: Yageo America; CompType: Resistor; Value: 40.7; Value_Code: 40R7; Tolerance_%: 0.1; Value2: 0.1W; VDC_V: 75; TempCo: 25 ppm/C; SizeArea_mm2: 1.28; SizeX_mm: 1.6; SizeY_mm: 0.8; SizeZ_mm: 1; EIA_Code: E192; U/M: EA; AEC Category: Q200
signal-integrity model Resistor
simulation model Resistor
footprint 0603
footprint 0603M
footprint 0603L
footprint 0603_HV
footprint 0603S
pins: 1, 2

## RT0603BRD0741K2L
designator R?  ValueDisplayed: 41.2k  (hidden comment: RT0603BRD0741K2L)
RES, 41.2 k, 0.1%, 0.1 W, 0603; Manufacturer: Yageo America; CompType: Resistor; Value: 41.2k; Res_ohm: 41200; Value_Code: 41k2; Tolerance_%: 0.1; Value2: 0.1W; VDC_V: 75; TempCo: 25 ppm/C; SizeArea_mm2: 1.28; SizeX_mm: 1.6; SizeY_mm: 0.8; SizeZ_mm: 1; EIA_Code: E192; U/M: EA; AEC Category: Q200
signal-integrity model Resistor
simulation model Resistor
footprint 0603
footprint 0603M
footprint 0603L
footprint 0603_HV
footprint 0603S
pins: 1, 2

## RT0603BRD0741K7L
designator R?  ValueDisplayed: 41.7k  (hidden comment: RT0603BRD0741K7L)
RES, 41.7 k, 0.1%, 0.1 W, 0603; Manufacturer: Yageo America; CompType: Resistor; Value: 41.7k; Res_ohm: 41700; Value_Code: 41k7; Tolerance_%: 0.1; Value2: 0.1W; VDC_V: 75; TempCo: 25 ppm/C; SizeArea_mm2: 1.28; SizeX_mm: 1.6; SizeY_mm: 0.8; SizeZ_mm: 1; EIA_Code: E192; U/M: EA; AEC Category: Q200
signal-integrity model Resistor
simulation model Resistor
footprint 0603
footprint 0603M
footprint 0603L
footprint 0603_HV
footprint 0603S
pins: 1, 2

## RT0603BRD0741R2L
designator R?  ValueDisplayed: 41.2  (hidden comment: RT0603BRD0741R2L)
RES, 41.2, 0.1%, 0.1 W, 0603; Manufacturer: Yageo America; CompType: Resistor; Value: 41.2; Value_Code: 41R2; Tolerance_%: 0.1; Value2: 0.1W; VDC_V: 75; TempCo: 25 ppm/C; SizeArea_mm2: 1.28; SizeX_mm: 1.6; SizeY_mm: 0.8; SizeZ_mm: 1; EIA_Code: E192; U/M: EA; AEC Category: Q200
signal-integrity model Resistor
simulation model Resistor
footprint 0603
footprint 0603M
footprint 0603L
footprint 0603_HV
footprint 0603S
pins: 1, 2

## RT0603BRD0741R7L
designator R?  ValueDisplayed: 41.7  (hidden comment: RT0603BRD0741R7L)
RES, 41.7, 0.1%, 0.1 W, 0603; Manufacturer: Yageo America; CompType: Resistor; Value: 41.7; Value_Code: 41R7; Tolerance_%: 0.1; Value2: 0.1W; VDC_V: 75; TempCo: 25 ppm/C; SizeArea_mm2: 1.28; SizeX_mm: 1.6; SizeY_mm: 0.8; SizeZ_mm: 1; EIA_Code: E192; U/M: EA; AEC Category: Q200
signal-integrity model Resistor
simulation model Resistor
footprint 0603
footprint 0603M
footprint 0603L
footprint 0603_HV
footprint 0603S
pins: 1, 2

## RT0603BRD0742K2L
designator R?  ValueDisplayed: 42.2k  (hidden comment: RT0603BRD0742K2L)
RES, 42.2 k, 0.1%, 0.1 W, 0603; Manufacturer: Yageo America; CompType: Resistor; Value: 42.2k; Res_ohm: 42200; Value_Code: 42k2; Tolerance_%: 0.1; Value2: 0.1W; VDC_V: 75; TempCo: 25 ppm/C; SizeArea_mm2: 1.28; SizeX_mm: 1.6; SizeY_mm: 0.8; SizeZ_mm: 1; EIA_Code: E192; U/M: EA; AEC Category: Q200
signal-integrity model Resistor
simulation model Resistor
footprint 0603
footprint 0603M
footprint 0603L
footprint 0603_HV
footprint 0603S
pins: 1, 2

## RT0603BRD0742K7L
designator R?  ValueDisplayed: 42.7k  (hidden comment: RT0603BRD0742K7L)
RES, 42.7 k, 0.1%, 0.1 W, 0603; Manufacturer: Yageo America; CompType: Resistor; Value: 42.7k; Res_ohm: 42700; Value_Code: 42k7; Tolerance_%: 0.1; Value2: 0.1W; VDC_V: 75; TempCo: 25 ppm/C; SizeArea_mm2: 1.28; SizeX_mm: 1.6; SizeY_mm: 0.8; SizeZ_mm: 1; EIA_Code: E192; U/M: EA; AEC Category: Q200
signal-integrity model Resistor
simulation model Resistor
footprint 0603
footprint 0603M
footprint 0603L
footprint 0603_HV
footprint 0603S
pins: 1, 2

## RT0603BRD0742R2L
designator R?  ValueDisplayed: 42.2  (hidden comment: RT0603BRD0742R2L)
RES, 42.2, 0.1%, 0.1 W, 0603; Manufacturer: Yageo America; CompType: Resistor; Value: 42.2; Value_Code: 42R2; Tolerance_%: 0.1; Value2: 0.1W; VDC_V: 75; TempCo: 25 ppm/C; SizeArea_mm2: 1.28; SizeX_mm: 1.6; SizeY_mm: 0.8; SizeZ_mm: 1; EIA_Code: E192; U/M: EA; AEC Category: Q200
signal-integrity model Resistor
simulation model Resistor
footprint 0603
footprint 0603M
footprint 0603L
footprint 0603_HV
footprint 0603S
pins: 1, 2

## RT0603BRD0742R7L
designator R?  ValueDisplayed: 42.7  (hidden comment: RT0603BRD0742R7L)
RES, 42.7, 0.1%, 0.1 W, 0603; Manufacturer: Yageo America; CompType: Resistor; Value: 42.7; Value_Code: 42R7; Tolerance_%: 0.1; Value2: 0.1W; VDC_V: 75; TempCo: 25 ppm/C; SizeArea_mm2: 1.28; SizeX_mm: 1.6; SizeY_mm: 0.8; SizeZ_mm: 1; EIA_Code: E192; U/M: EA; AEC Category: Q200
signal-integrity model Resistor
simulation model Resistor
footprint 0603
footprint 0603M
footprint 0603L
footprint 0603_HV
footprint 0603S
pins: 1, 2

## RT0603BRD0743K2L
designator R?  ValueDisplayed: 43.2k  (hidden comment: RT0603BRD0743K2L)
RES, 43.2 k, 0.1%, 0.1 W, 0603; Manufacturer: Yageo America; CompType: Resistor; Value: 43.2k; Res_ohm: 43200; Value_Code: 43k2; Tolerance_%: 0.1; Value2: 0.1W; VDC_V: 75; TempCo: 25 ppm/C; SizeArea_mm2: 1.28; SizeX_mm: 1.6; SizeY_mm: 0.8; SizeZ_mm: 1; EIA_Code: E192; U/M: EA; AEC Category: Q200
signal-integrity model Resistor
simulation model Resistor
footprint 0603
footprint 0603M
footprint 0603L
footprint 0603_HV
footprint 0603S
pins: 1, 2

## RT0603BRD0743K7L
designator R?  ValueDisplayed: 43.7k  (hidden comment: RT0603BRD0743K7L)
RES, 43.7 k, 0.1%, 0.1 W, 0603; Manufacturer: Yageo America; CompType: Resistor; Value: 43.7k; Res_ohm: 43700; Value_Code: 43k7; Tolerance_%: 0.1; Value2: 0.1W; VDC_V: 75; TempCo: 25 ppm/C; SizeArea_mm2: 1.28; SizeX_mm: 1.6; SizeY_mm: 0.8; SizeZ_mm: 1; EIA_Code: E192; U/M: EA; AEC Category: Q200
signal-integrity model Resistor
simulation model Resistor
footprint 0603
footprint 0603M
footprint 0603L
footprint 0603_HV
footprint 0603S
pins: 1, 2

## RT0603BRD0743R2L
designator R?  ValueDisplayed: 43.2  (hidden comment: RT0603BRD0743R2L)
RES, 43.2, 0.1%, 0.1 W, 0603; Manufacturer: Yageo America; CompType: Resistor; Value: 43.2; Value_Code: 43R2; Tolerance_%: 0.1; Value2: 0.1W; VDC_V: 75; TempCo: 25 ppm/C; SizeArea_mm2: 1.28; SizeX_mm: 1.6; SizeY_mm: 0.8; SizeZ_mm: 1; EIA_Code: E192; U/M: EA; AEC Category: Q200; Green_Lifecycle: Active; Green_REACh: Passed
signal-integrity model Resistor
simulation model Resistor
footprint 0603
footprint 0603M
footprint 0603L
footprint 0603_HV
footprint 0603S
pins: 1, 2

## RT0603BRD0743R7L
designator R?  ValueDisplayed: 43.7  (hidden comment: RT0603BRD0743R7L)
RES, 43.7, 0.1%, 0.1 W, 0603; Manufacturer: Yageo America; CompType: Resistor; Value: 43.7; Value_Code: 43R7; Tolerance_%: 0.1; Value2: 0.1W; VDC_V: 75; TempCo: 25 ppm/C; SizeArea_mm2: 1.28; SizeX_mm: 1.6; SizeY_mm: 0.8; SizeZ_mm: 1; EIA_Code: E192; U/M: EA; AEC Category: Q200
signal-integrity model Resistor
simulation model Resistor
footprint 0603
footprint 0603M
footprint 0603L
footprint 0603_HV
footprint 0603S
pins: 1, 2

## RT0603BRD0744K2L
designator R?  ValueDisplayed: 44.2k  (hidden comment: RT0603BRD0744K2L)
RES, 44.2 k, 0.1%, 0.1 W, 0603; Manufacturer: Yageo America; CompType: Resistor; Value: 44.2k; Res_ohm: 44200; Value_Code: 44k2; Tolerance_%: 0.1; Value2: 0.1W; VDC_V: 75; TempCo: 25 ppm/C; SizeArea_mm2: 1.28; SizeX_mm: 1.6; SizeY_mm: 0.8; SizeZ_mm: 1; EIA_Code: E192; U/M: EA; AEC Category: Q200
signal-integrity model Resistor
simulation model Resistor
footprint 0603
footprint 0603M
footprint 0603L
footprint 0603_HV
footprint 0603S
pins: 1, 2

## RT0603BRD0744K8L
designator R?  ValueDisplayed: 44.8k  (hidden comment: RT0603BRD0744K8L)
RES, 44.8 k, 0.1%, 0.1 W, 0603; Manufacturer: Yageo America; CompType: Resistor; Value: 44.8k; Res_ohm: 44800; Value_Code: 44k8; Tolerance_%: 0.1; Value2: 0.1W; VDC_V: 75; TempCo: 25 ppm/C; SizeArea_mm2: 1.28; SizeX_mm: 1.6; SizeY_mm: 0.8; SizeZ_mm: 1; EIA_Code: E192; U/M: EA; AEC Category: Q200
signal-integrity model Resistor
simulation model Resistor
footprint 0603
footprint 0603M
footprint 0603L
footprint 0603_HV
footprint 0603S
pins: 1, 2

## RT0603BRD0744R2L
designator R?  ValueDisplayed: 44.2  (hidden comment: RT0603BRD0744R2L)
RES, 44.2, 0.1%, 0.1 W, 0603; Manufacturer: Yageo America; CompType: Resistor; Value: 44.2; Value_Code: 44R2; Tolerance_%: 0.1; Value2: 0.1W; VDC_V: 75; TempCo: 25 ppm/C; SizeArea_mm2: 1.28; SizeX_mm: 1.6; SizeY_mm: 0.8; SizeZ_mm: 1; EIA_Code: E192; U/M: EA; AEC Category: Q200
signal-integrity model Resistor
simulation model Resistor
footprint 0603
footprint 0603M
footprint 0603L
footprint 0603_HV
footprint 0603S
pins: 1, 2

## RT0603BRD0744R8L
designator R?  ValueDisplayed: 44.8  (hidden comment: RT0603BRD0744R8L)
RES, 44.8, 0.1%, 0.1 W, 0603; Manufacturer: Yageo America; CompType: Resistor; Value: 44.8; Value_Code: 44R8; Tolerance_%: 0.1; Value2: 0.1W; VDC_V: 75; TempCo: 25 ppm/C; SizeArea_mm2: 1.28; SizeX_mm: 1.6; SizeY_mm: 0.8; SizeZ_mm: 1; EIA_Code: E192; U/M: EA; AEC Category: Q200
signal-integrity model Resistor
simulation model Resistor
footprint 0603
footprint 0603M
footprint 0603L
footprint 0603_HV
footprint 0603S
pins: 1, 2

## RT0603BRD0745K3L
designator R?  ValueDisplayed: 45.3k  (hidden comment: RT0603BRD0745K3L)
RES, 45.3 k, 0.1%, 0.1 W, 0603; Manufacturer: Yageo America; CompType: Resistor; Value: 45.3k; Res_ohm: 45300; Value_Code: 45k3; Tolerance_%: 0.1; Value2: 0.1W; VDC_V: 75; TempCo: 25 ppm/C; SizeArea_mm2: 1.28; SizeX_mm: 1.6; SizeY_mm: 0.8; SizeZ_mm: 1; EIA_Code: E192; U/M: EA; AEC Category: Q200
signal-integrity model Resistor
simulation model Resistor
footprint 0603
footprint 0603M
footprint 0603L
footprint 0603_HV
footprint 0603S
pins: 1, 2

## RT0603BRD0745K9L
designator R?  ValueDisplayed: 45.9k  (hidden comment: RT0603BRD0745K9L)
RES, 45.9 k, 0.1%, 0.1 W, 0603; Manufacturer: Yageo America; CompType: Resistor; Value: 45.9k; Res_ohm: 45900; Value_Code: 45k9; Tolerance_%: 0.1; Value2: 0.1W; VDC_V: 75; TempCo: 25 ppm/C; SizeArea_mm2: 1.28; SizeX_mm: 1.6; SizeY_mm: 0.8; SizeZ_mm: 1; EIA_Code: E192; U/M: EA; AEC Category: Q200
signal-integrity model Resistor
simulation model Resistor
footprint 0603
footprint 0603M
footprint 0603L
footprint 0603_HV
footprint 0603S
pins: 1, 2

## RT0603BRD0745R3L
designator R?  ValueDisplayed: 45.3  (hidden comment: RT0603BRD0745R3L)
RES, 45.3, 0.1%, 0.1 W, 0603; Manufacturer: Yageo America; CompType: Resistor; Value: 45.3; Value_Code: 45R3; Tolerance_%: 0.1; Value2: 0.1W; VDC_V: 75; TempCo: 25 ppm/C; SizeArea_mm2: 1.28; SizeX_mm: 1.6; SizeY_mm: 0.8; SizeZ_mm: 1; EIA_Code: E192; U/M: EA; AEC Category: Q200
signal-integrity model Resistor
simulation model Resistor
footprint 0603
footprint 0603M
footprint 0603L
footprint 0603_HV
footprint 0603S
pins: 1, 2

## RT0603BRD0745R9L
designator R?  ValueDisplayed: 45.9  (hidden comment: RT0603BRD0745R9L)
RES, 45.9, 0.1%, 0.1 W, 0603; Manufacturer: Yageo America; CompType: Resistor; Value: 45.9; Value_Code: 45R9; Tolerance_%: 0.1; Value2: 0.1W; VDC_V: 75; TempCo: 25 ppm/C; SizeArea_mm2: 1.28; SizeX_mm: 1.6; SizeY_mm: 0.8; SizeZ_mm: 1; EIA_Code: E192; U/M: EA; AEC Category: Q200
signal-integrity model Resistor
simulation model Resistor
footprint 0603
footprint 0603M
footprint 0603L
footprint 0603_HV
footprint 0603S
pins: 1, 2

## RT0603BRD0746K4L
designator R?  ValueDisplayed: 46.4k  (hidden comment: RT0603BRD0746K4L)
RES, 46.4 k, 0.1%, 0.1 W, 0603; Manufacturer: Yageo America; CompType: Resistor; Value: 46.4k; Res_ohm: 46400; Value_Code: 46k4; Tolerance_%: 0.1; Value2: 0.1W; VDC_V: 75; TempCo: 25 ppm/C; SizeArea_mm2: 1.28; SizeX_mm: 1.6; SizeY_mm: 0.8; SizeZ_mm: 1; EIA_Code: E192; U/M: EA; AEC Category: Q200
signal-integrity model Resistor
simulation model Resistor
footprint 0603
footprint 0603M
footprint 0603L
footprint 0603_HV
footprint 0603S
pins: 1, 2

## RT0603BRD0746R4L
designator R?  ValueDisplayed: 46.4  (hidden comment: RT0603BRD0746R4L)
RES, 46.4, 0.1%, 0.1 W, 0603; Manufacturer: Yageo America; CompType: Resistor; Value: 46.4; Value_Code: 46R4; Tolerance_%: 0.1; Value2: 0.1W; VDC_V: 75; TempCo: 25 ppm/C; SizeArea_mm2: 1.28; SizeX_mm: 1.6; SizeY_mm: 0.8; SizeZ_mm: 1; EIA_Code: E192; U/M: EA; AEC Category: Q200
signal-integrity model Resistor
simulation model Resistor
footprint 0603
footprint 0603M
footprint 0603L
footprint 0603_HV
footprint 0603S
pins: 1, 2

## RT0603BRD0747K5L
designator R?  ValueDisplayed: 47.5k  (hidden comment: RT0603BRD0747K5L)
RES, 47.5 k, 0.1%, 0.1 W, 0603; Manufacturer: Yageo America; CompType: Resistor; Value: 47.5k; Res_ohm: 47500; Value_Code: 47k5; Tolerance_%: 0.1; Value2: 0.1W; VDC_V: 75; TempCo: 25 ppm/C; SizeArea_mm2: 1.28; SizeX_mm: 1.6; SizeY_mm: 0.8; SizeZ_mm: 1; EIA_Code: E192; U/M: EA; AEC Category: Q200
signal-integrity model Resistor
simulation model Resistor
footprint 0603
footprint 0603M
footprint 0603L
footprint 0603_HV
footprint 0603S
pins: 1, 2

## RT0603BRD0747KL
designator R?  ValueDisplayed: 47.0k  (hidden comment: RT0603BRD0747KL)
RES, 47.0 k, 0.1%, 0.1 W, 0603; Manufacturer: Yageo America; CompType: Resistor; Value: 47.0k; Res_ohm: 47000; Value_Code: 47k0; Tolerance_%: 0.1; Value2: 0.1W; VDC_V: 75; TempCo: 25 ppm/C; SizeArea_mm2: 1.28; SizeX_mm: 1.6; SizeY_mm: 0.8; SizeZ_mm: 1; EIA_Code: E192; U/M: EA; AEC Category: Q200
signal-integrity model Resistor
simulation model Resistor
footprint 0603
footprint 0603M
footprint 0603L
footprint 0603_HV
footprint 0603S
pins: 1, 2

## RT0603BRD0747R5L
designator R?  ValueDisplayed: 47.5  (hidden comment: RT0603BRD0747R5L)
RES, 47.5, 0.1%, 0.1 W, 0603; Manufacturer: Yageo America; CompType: Resistor; Value: 47.5; Value_Code: 47R5; Tolerance_%: 0.1; Value2: 0.1W; VDC_V: 75; TempCo: 25 ppm/C; SizeArea_mm2: 1.28; SizeX_mm: 1.6; SizeY_mm: 0.8; SizeZ_mm: 1; EIA_Code: E192; U/M: EA; AEC Category: Q200
signal-integrity model Resistor
simulation model Resistor
footprint 0603
footprint 0603M
footprint 0603L
footprint 0603_HV
footprint 0603S
pins: 1, 2

## RT0603BRD0747RL
designator R?  ValueDisplayed: 47.0  (hidden comment: RT0603BRD0747RL)
RES, 47.0, 0.1%, 0.1 W, 0603; Manufacturer: Yageo America; CompType: Resistor; Value: 47.0; Res_ohm: 47; Value_Code: 47R0; Tolerance_%: 0.1; Value2: 0.1W; VDC_V: 75; TempCo: 25 ppm/C; SizeArea_mm2: 1.28; SizeX_mm: 1.6; SizeY_mm: 0.8; SizeZ_mm: 1; EIA_Code: E192; U/M: EA; AEC Category: Q200
signal-integrity model Resistor
simulation model Resistor
footprint 0603
footprint 0603M
footprint 0603L
footprint 0603_HV
footprint 0603S
pins: 1, 2

## RT0603BRD0748K1L
designator R?  ValueDisplayed: 48.1k  (hidden comment: RT0603BRD0748K1L)
RES, 48.1 k, 0.1%, 0.1 W, 0603; Manufacturer: Yageo America; CompType: Resistor; Value: 48.1k; Res_ohm: 48100; Value_Code: 48k1; Tolerance_%: 0.1; Value2: 0.1W; VDC_V: 75; TempCo: 25 ppm/C; SizeArea_mm2: 1.28; SizeX_mm: 1.6; SizeY_mm: 0.8; SizeZ_mm: 1; EIA_Code: E192; U/M: EA; AEC Category: Q200
signal-integrity model Resistor
simulation model Resistor
footprint 0603
footprint 0603M
footprint 0603L
footprint 0603_HV
footprint 0603S
pins: 1, 2

## RT0603BRD0748K7L
designator R?  ValueDisplayed: 48.7k  (hidden comment: RT0603BRD0748K7L)
RES, 48.7 k, 0.1%, 0.1 W, 0603; Manufacturer: Yageo America; CompType: Resistor; Value: 48.7k; Res_ohm: 48700; Value_Code: 48k7; Tolerance_%: 0.1; Value2: 0.1W; VDC_V: 75; TempCo: 25 ppm/C; SizeArea_mm2: 1.28; SizeX_mm: 1.6; SizeY_mm: 0.8; SizeZ_mm: 1; EIA_Code: E192; U/M: EA; AEC Category: Q200
signal-integrity model Resistor
simulation model Resistor
footprint 0603
footprint 0603M
footprint 0603L
footprint 0603_HV
footprint 0603S
pins: 1, 2

## RT0603BRD0748R1L
designator R?  ValueDisplayed: 48.1  (hidden comment: RT0603BRD0748R1L)
RES, 48.1, 0.1%, 0.1 W, 0603; Manufacturer: Yageo America; CompType: Resistor; Value: 48.1; Value_Code: 48R1; Tolerance_%: 0.1; Value2: 0.1W; VDC_V: 75; TempCo: 25 ppm/C; SizeArea_mm2: 1.28; SizeX_mm: 1.6; SizeY_mm: 0.8; SizeZ_mm: 1; EIA_Code: E192; U/M: EA; AEC Category: Q200
signal-integrity model Resistor
simulation model Resistor
footprint 0603
footprint 0603M
footprint 0603L
footprint 0603_HV
footprint 0603S
pins: 1, 2

## RT0603BRD0748R7L
designator R?  ValueDisplayed: 48.7  (hidden comment: RT0603BRD0748R7L)
RES, 48.7, 0.1%, 0.1 W, 0603; Manufacturer: Yageo America; CompType: Resistor; Value: 48.7; Value_Code: 48R7; Tolerance_%: 0.1; Value2: 0.1W; VDC_V: 75; TempCo: 25 ppm/C; SizeArea_mm2: 1.28; SizeX_mm: 1.6; SizeY_mm: 0.8; SizeZ_mm: 1; EIA_Code: E192; U/M: EA; AEC Category: Q200
signal-integrity model Resistor
simulation model Resistor
footprint 0603
footprint 0603M
footprint 0603L
footprint 0603_HV
footprint 0603S
pins: 1, 2

## RT0603BRD0749K3L
designator R?  ValueDisplayed: 49.3k  (hidden comment: RT0603BRD0749K3L)
RES, 49.3 k, 0.1%, 0.1 W, 0603; Manufacturer: Yageo America; CompType: Resistor; Value: 49.3k; Res_ohm: 49300; Value_Code: 49k3; Tolerance_%: 0.1; Value2: 0.1W; VDC_V: 75; TempCo: 25 ppm/C; SizeArea_mm2: 1.28; SizeX_mm: 1.6; SizeY_mm: 0.8; SizeZ_mm: 1; EIA_Code: E192; U/M: EA; AEC Category: Q200
signal-integrity model Resistor
simulation model Resistor
footprint 0603
footprint 0603M
footprint 0603L
footprint 0603_HV
footprint 0603S
pins: 1, 2

## RT0603BRD0749K9L
designator R?  ValueDisplayed: 49.9k  (hidden comment: RT0603BRD0749K9L)
RES, 49.9 k, 0.1%, 0.1 W, 0603; Manufacturer: Yageo America; CompType: Resistor; Value: 49.9k; Res_ohm: 49900; Value_Code: 49k9; Tolerance_%: 0.1; Value2: 0.1W; VDC_V: 75; TempCo: 25 ppm/C; SizeArea_mm2: 1.28; SizeX_mm: 1.6; SizeY_mm: 0.8; SizeZ_mm: 1; EIA_Code: E192; U/M: EA; AEC Category: Q200
signal-integrity model Resistor
simulation model Resistor
footprint 0603
footprint 0603M
footprint 0603L
footprint 0603_HV
footprint 0603S
pins: 1, 2

## RT0603BRD0749R3L
designator R?  ValueDisplayed: 49.3  (hidden comment: RT0603BRD0749R3L)
RES, 49.3, 0.1%, 0.1 W, 0603; Manufacturer: Yageo America; CompType: Resistor; Value: 49.3; Value_Code: 49R3; Tolerance_%: 0.1; Value2: 0.1W; VDC_V: 75; TempCo: 25 ppm/C; SizeArea_mm2: 1.28; SizeX_mm: 1.6; SizeY_mm: 0.8; SizeZ_mm: 1; EIA_Code: E192; U/M: EA; AEC Category: Q200
signal-integrity model Resistor
simulation model Resistor
footprint 0603
footprint 0603M
footprint 0603L
footprint 0603_HV
footprint 0603S
pins: 1, 2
